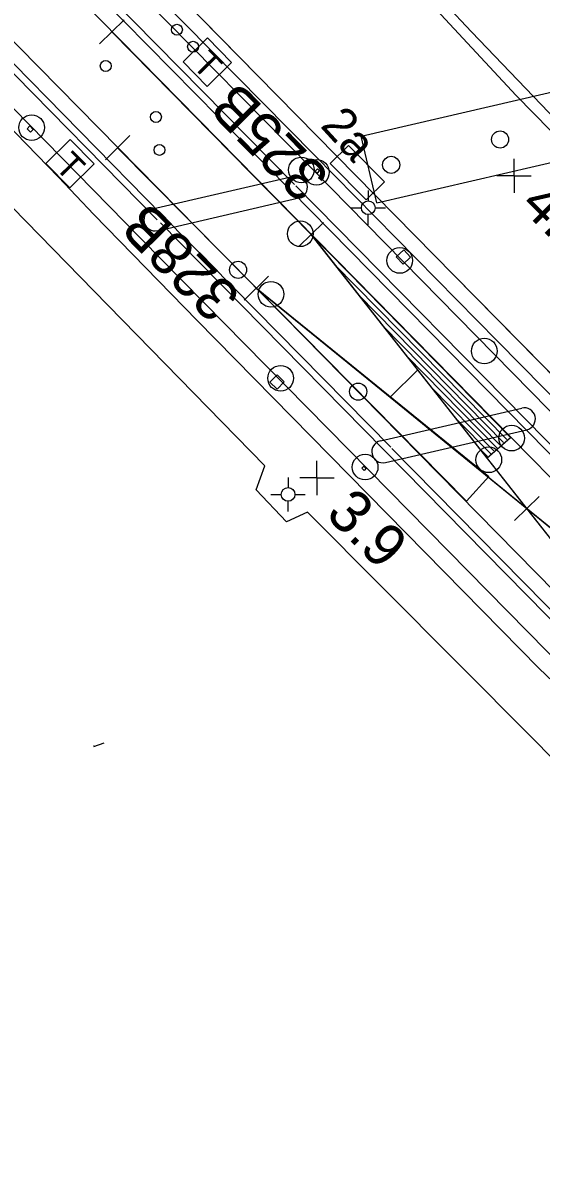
# Model space of a CAD drawing. Extents: x 1596643 to 1597288, y 13057194 to 13057957.
# Drawn here: x 1596964.2 to 1596994.5, y 13057338.6 to 13057405.5 of the extents above; entities that cross this region are included whole.
import ezdxf

# ---------------------------------------------------------------- set-up
doc = ezdxf.new("R2010")
doc.units = 0
for name, color, linetype in [('A Isolerskarv P', 7, 'Continuous'), ('A spårmitt L', 7, 'Continuous'), ('B Vxl-symbol P', 7, 'Continuous'), ('B växel linjevikt 0 L', 7, 'Continuous'), ('B Växel nr T', 7, 'Continuous'), ('BAS belysningsstolpe P', 7, 'Continuous'), ('BAS bro kantbalk ej def L', 7, 'Continuous'), ('BAS bropelare stöd ej def L', 7, 'Continuous'), ('BAS dagvatten brunn P', 7, 'Continuous'), ('BAS jvg-bro kantbalk L', 7, 'Continuous'), ('BAS Level 15', 7, 'Continuous'), ('BAS Level 16', 7, 'Continuous'), ('BAS Level 19', 7, 'Continuous'), ('BAS Level 29', 7, 'Continuous'), ('BAS markytetext T', 7, 'Continuous'), ('BAS registerområdesgräns L', 7, 'Continuous'), ('BAS väg-bro kantbalk L', 7, 'Continuous'), ('BAS väg-bro pelare stöd L', 7, 'Continuous'), ('BAS vägbanekant L', 7, 'Continuous'), ('E ktl sträva stag fundament L', 7, 'Continuous'), ('E ktlstolpe normal centrum P', 7, 'Continuous'), ('E ktlstolpe T', 7, 'Continuous'), ('G telefon fristående P', 7, 'Continuous')]:
    doc.layers.add(name, color=color, linetype=linetype)

msp = doc.modelspace()

# ---------------------------------------------------------------- linework, layer by layer
at = {"layer": 'A Isolerskarv P'}
for centre in [(1596980.436, 13057393.226), (1596980.436, 13057393.226), (1596978.723, 13057389.694), (1596978.723, 13057389.694), (1596992.779, 13057381.288), (1596992.779, 13057381.288), (1596991.445, 13057380.023), (1596991.445, 13057380.023)]:
    msp.add_circle(centre, 0.75, dxfattribs=at)
at = {"layer": 'A spårmitt L'}
for p, q in [((1596970.138, 13057405.733), (1596968.711, 13057404.331)), ((1596970.138, 13057405.733), (1596968.711, 13057404.331)), ((1596969.424, 13057405.032), (1596981.072, 13057393.183)), ((1596969.424, 13057405.032), (1596981.072, 13057393.183)), ((1596980.359, 13057392.482), (1596981.785, 13057393.884)), ((1596980.359, 13057392.482), (1596981.785, 13057393.884)), ((1597006.272, 13057361.158), (1596981.072, 13057393.183)), ((1596981.072, 13057393.183), (1596992.72, 13057381.334)), ((1596981.072, 13057393.183), (1596991.339, 13057380.121)), ((1596981.072, 13057393.183), (1596992.72, 13057381.334)), ((1596981.072, 13057393.183), (1596991.339, 13057380.121)), ((1596982.432, 13057391.435), (1596992.493, 13057381.201)), ((1596982.432, 13057391.435), (1596992.493, 13057381.201)), ((1597009.479, 13057364.305), (1596977.865, 13057390.027)), ((1596983.831, 13057389.656), (1596992.305, 13057381.035)), ((1596983.831, 13057389.656), (1596992.305, 13057381.035)), ((1596985.23, 13057387.876), (1596992.117, 13057380.87)), ((1596985.23, 13057387.876), (1596992.117, 13057380.87)), ((1596986.63, 13057386.096), (1596991.929, 13057380.705)), ((1596986.63, 13057386.096), (1596991.929, 13057380.705)), ((1596988.029, 13057384.316), (1596991.741, 13057380.539)), ((1596988.029, 13057384.316), (1596991.741, 13057380.539)), ((1596989.574, 13057382.387), (1596991.563, 13057380.364)), ((1596989.574, 13057382.387), (1596991.563, 13057380.364)), ((1596991.339, 13057380.121), (1596992.72, 13057381.334)), ((1596991.339, 13057380.121), (1596992.72, 13057381.334)), ((1596990.827, 13057380.757), (1596991.365, 13057380.209)), ((1596990.827, 13057380.757), (1596991.365, 13057380.209))]:
    msp.add_line(p, q, dxfattribs=at)
for points in [[(1596887.988, 13057492.75), (1596889.66, 13057490.516), (1596900.094, 13057476.776), (1596906.53, 13057469.464), (1596928.328, 13057446.663), (1596936.899, 13057437.942), (1596957.336, 13057417.351), (1597001.928, 13057371.989), (1597034.879, 13057338.506), (1597063.764, 13057309.15)], [(1596933.802, 13057434.837), (1596974.458, 13057393.515), (1596978.362, 13057389.553), (1596998.703, 13057368.849), (1597057.437, 13057309.15)]]:
    msp.add_lwpolyline(points, dxfattribs=at)
at = {"layer": 'B Vxl-symbol P'}
for p, q in [((1596987.305, 13057385.289), (1596985.677, 13057383.692)), ((1596993.672, 13057377.17), (1596987.305, 13057385.289)), ((1596985.677, 13057383.692), (1596993.672, 13057377.17)), ((1596985.736, 13057383.643), (1596985.689, 13057383.704)), ((1596992.958, 13057376.47), (1596994.386, 13057377.871)), ((1596993.672, 13057377.17), (1597001.667, 13057370.649)), ((1597000.039, 13057369.052), (1596993.672, 13057377.17))]:
    msp.add_line(p, q, dxfattribs=at)
at = {"layer": 'B växel linjevikt 0 L'}
for p, q in [((1596970.476, 13057398.962), (1596969.052, 13057397.556)), ((1596970.476, 13057398.962), (1596969.052, 13057397.556)), ((1596969.764, 13057398.259), (1596977.873, 13057390.048)), ((1596969.764, 13057398.259), (1596977.873, 13057390.048)), ((1596978.584, 13057390.751), (1596977.161, 13057389.346)), ((1596978.584, 13057390.751), (1596977.161, 13057389.346)), ((1596977.873, 13057390.048), (1596990.152, 13057377.615)), ((1596977.873, 13057390.048), (1596990.152, 13057377.615)), ((1596977.873, 13057390.048), (1596991.45, 13057379.047)), ((1596977.873, 13057390.048), (1596990.152, 13057377.615)), ((1596977.873, 13057390.048), (1596991.45, 13057379.047)), ((1596990.152, 13057377.615), (1596991.45, 13057379.047)), ((1596990.152, 13057377.615), (1596991.45, 13057379.047)), ((1596991.45, 13057379.047), (1596990.152, 13057377.615)), ((1596990.152, 13057377.615), (1596991.45, 13057379.047))]:
    msp.add_line(p, q, dxfattribs=at)
at = {"layer": 'BAS belysningsstolpe P'}
for p, q in [((1596984.403, 13057395.75), (1596984.403, 13057395.15)), ((1596984.403, 13057395.75), (1596984.403, 13057395.15)), ((1596983.403, 13057394.75), (1596984.003, 13057394.75)), ((1596983.403, 13057394.75), (1596984.003, 13057394.75)), ((1596984.403, 13057393.75), (1596984.403, 13057394.352)), ((1596984.403, 13057393.75), (1596984.403, 13057394.352)), ((1596984.802, 13057394.75), (1596985.403, 13057394.75)), ((1596984.802, 13057394.75), (1596985.403, 13057394.75)), ((1596979.72, 13057378.998), (1596979.72, 13057378.398)), ((1596979.72, 13057378.998), (1596979.72, 13057378.398)), ((1596978.72, 13057377.998), (1596979.32, 13057377.998)), ((1596978.72, 13057377.998), (1596979.32, 13057377.998)), ((1596980.119, 13057377.998), (1596980.72, 13057377.998)), ((1596980.119, 13057377.998), (1596980.72, 13057377.998)), ((1596979.72, 13057376.998), (1596979.72, 13057377.6)), ((1596979.72, 13057376.998), (1596979.72, 13057377.6))]:
    msp.add_line(p, q, dxfattribs=at)
for centre in [(1596984.403, 13057394.75), (1596984.403, 13057394.75), (1596979.72, 13057377.998), (1596979.72, 13057377.998)]:
    msp.add_circle(centre, 0.4, dxfattribs=at)
at = {"layer": 'BAS bro kantbalk ej def L'}
for p, q in [((1596969.424, 13057408.898), (1596981.122, 13057397.026)), ((1596979.817, 13057395.82), (1596967.801, 13057408.027)), ((1596968.086, 13057408.307), (1596980.102, 13057396.1)), ((1596960.381, 13057406.522), (1596972.364, 13057394.325)), ((1596972.078, 13057394.045), (1596960.095, 13057406.241)), ((1596971.144, 13057392.936), (1596958.939, 13057405.365)), ((1596981.122, 13057397.026), (1596993.879, 13057384.028)), ((1597006.479, 13057368.704), (1596979.888, 13057395.753)), ((1596980.172, 13057396.033), (1597006.764, 13057368.984)), ((1596998.725, 13057366.965), (1596972.262, 13057393.865)), ((1596985.715, 13057380.76), (1596972.548, 13057394.146)), ((1596984.462, 13057379.392), (1596971.144, 13057392.936)), ((1596993.879, 13057384.028), (1597007.761, 13057369.925)), ((1596999.011, 13057367.246), (1596985.788, 13057380.683)), ((1596997.782, 13057365.837), (1596984.462, 13057379.392))]:
    msp.add_line(p, q, dxfattribs=at)
msp.add_lwpolyline([(1597031.744, 13057325.449), (1597019.684, 13057337.598), (1597007.4, 13057349.92), (1597006.374, 13057349.4), (1597004.663, 13057351.16), (1597005.204, 13057352.357), (1596994.028, 13057363.747)], dxfattribs=at)
at = {"layer": 'BAS bropelare stöd ej def L'}
for p, q in [((1596971.801, 13057394.677), (1596980.06, 13057396.588)), ((1596972.09, 13057393.41), (1596980.351, 13057395.321)), ((1596985.115, 13057381.134), (1596993.373, 13057383.044)), ((1596985.404, 13057379.866), (1596993.665, 13057381.777))]:
    msp.add_line(p, q, dxfattribs=at)
for centre, start, end in [((1596980.204, 13057395.954), 283.02596, 103.02572), ((1596971.948, 13057394.044), 103.02596, 283.02572), ((1596993.518, 13057382.411), 283.02596, 103.02572), ((1596985.261, 13057380.5), 103.02596, 283.02572)]:
    msp.add_arc(centre, 0.65, start, end, dxfattribs=at)
at = {"layer": 'BAS dagvatten brunn P'}
msp.add_line((1596983.762, 13057396.8), (1596983.762, 13057396.8), dxfattribs=at)
msp.add_line((1596983.762, 13057396.8), (1596983.762, 13057396.8), dxfattribs=at)
msp.add_lwpolyline([(1596982.175, 13057397.343), (1596984.28, 13057395.205), (1596985.349, 13057396.257), (1596983.244, 13057398.395)], close=True, dxfattribs=at)
msp.add_lwpolyline([(1596982.175, 13057397.343), (1596984.28, 13057395.205), (1596985.349, 13057396.257), (1596983.244, 13057398.395)], close=True, dxfattribs=at)
at = {"layer": 'BAS jvg-bro kantbalk L'}
for p, q in [((1596970.562, 13057408.681), (1596981.271, 13057397.819)), ((1596981.271, 13057397.819), (1596991.946, 13057386.955)), ((1596991.946, 13057386.955), (1597003.562, 13057375.151))]:
    msp.add_line(p, q, dxfattribs=at)
at = {"layer": 'BAS Level 15'}
for centre in [(1596976.801, 13057391.125), (1596976.801, 13057391.125), (1596983.814, 13057384.004), (1596983.814, 13057384.004)]:
    msp.add_circle(centre, 0.5, dxfattribs=at)
at = {"layer": 'BAS Level 16'}
for p, q in [((1596992.924, 13057396.615), (1596992.924, 13057397.615)), ((1596992.924, 13057396.615), (1596992.924, 13057397.615)), ((1596992.924, 13057396.615), (1596991.924, 13057396.615)), ((1596992.924, 13057396.615), (1596991.924, 13057396.615)), ((1596992.924, 13057396.615), (1596993.924, 13057396.615)), ((1596992.924, 13057396.615), (1596992.924, 13057395.615)), ((1596992.924, 13057396.615), (1596993.924, 13057396.615)), ((1596992.924, 13057396.615), (1596992.924, 13057395.615)), ((1596981.408, 13057378.966), (1596981.408, 13057379.966)), ((1596981.408, 13057378.966), (1596981.408, 13057379.966)), ((1596981.408, 13057378.966), (1596980.408, 13057378.966)), ((1596981.408, 13057378.966), (1596980.408, 13057378.966)), ((1596981.408, 13057378.966), (1596982.408, 13057378.966)), ((1596981.408, 13057378.966), (1596981.408, 13057377.966)), ((1596981.408, 13057378.966), (1596982.408, 13057378.966)), ((1596981.408, 13057378.966), (1596981.408, 13057377.966))]:
    msp.add_line(p, q, dxfattribs=at)
at = {"layer": 'BAS Level 19'}
for points in [[(1596968.373, 13057394.355), (1596966.305, 13057396.53), (1596963.82, 13057399.106), (1596961.488, 13057401.488), (1596960.235, 13057402.746)], [(1596996.958, 13057365.38), (1596994.369, 13057367.841), (1596974.42, 13057388.153), (1596968.373, 13057394.355)]]:
    msp.add_lwpolyline(points, dxfattribs=at)
at = {"layer": 'BAS Level 29'}
for centre in [(1596973.23, 13057405.151), (1596973.23, 13057405.151), (1596974.171, 13057404.159), (1596974.171, 13057404.159), (1596969.068, 13057403.032), (1596969.068, 13057403.032), (1596972.001, 13057400.052), (1596972.001, 13057400.052), (1596972.209, 13057398.13), (1596972.209, 13057398.13)]:
    msp.add_circle(centre, 0.318, dxfattribs=at)
at = {"layer": 'BAS registerområdesgräns L'}
for points in [[(1596968.373, 13057363.272), (1596968.974, 13057363.476)], [(1596968.398, 13057363.323), (1596968.373, 13057363.315)]]:
    msp.add_lwpolyline(points, dxfattribs=at)
at = {"layer": 'BAS väg-bro kantbalk L'}
for points in [[(1596968.373, 13057389.891), (1596958.042, 13057400.461)], [(1596994.028, 13057363.747), (1596980.859, 13057376.954), (1596979.62, 13057376.393), (1596977.859, 13057378.26), (1596978.355, 13057379.663), (1596968.373, 13057389.891)]]:
    msp.add_lwpolyline(points, dxfattribs=at)
at = {"layer": 'BAS väg-bro pelare stöd L'}
for p, q in [((1596984, 13057398.936), (1597005.371, 13057403.887)), ((1596984.906, 13057395.04), (1597006.278, 13057399.991)), ((1596984.906, 13057395.04), (1596984, 13057398.936))]:
    msp.add_line(p, q, dxfattribs=at)
for centre in [(1596992.106, 13057398.735), (1596985.742, 13057397.258)]:
    msp.add_circle(centre, 0.5, dxfattribs=at)
at = {"layer": 'BAS vägbanekant L'}
for p, q in [((1596977.952, 13057402.455), (1596970.491, 13057410.065)), ((1596989.414, 13057390.809), (1596977.952, 13057402.455)), ((1597002.777, 13057377.214), (1596989.414, 13057390.809))]:
    msp.add_line(p, q, dxfattribs=at)
for points in [[(1597133.452, 13057259.15), (1597054.729, 13057339.299), (1596995.848, 13057399.372), (1596990.433, 13057405.034), (1596987.369, 13057408.321), (1596983.644, 13057412.319), (1596981.852, 13057414.308), (1596980.193, 13057416.206), (1596978.635, 13057418.012), (1596978.187, 13057418.58), (1596977.383, 13057419.585), (1596976.059, 13057421.351), (1596974.481, 13057423.493), (1596972.433, 13057426.487), (1596969.826, 13057430.508), (1596968.373, 13057432.851)], [(1596968.373, 13057431.554), (1596968.412, 13057431.491), (1596970.968, 13057427.583), (1596973.443, 13057423.938), (1596974.798, 13057422.081), (1596976.844, 13057419.442), (1596978.382, 13057417.442), (1596980.143, 13057415.392), (1596981.65, 13057413.616), (1596983.899, 13057411.12), (1596986.841, 13057408.015), (1596993.05, 13057401.308), (1597001.071, 13057393.121), (1597017.407, 13057376.512), (1597028.562, 13057365.159), (1597039.891, 13057353.552), (1597050.384, 13057342.909), (1597065.285, 13057327.589), (1597082.629, 13057309.925), (1597099.189, 13057293.124), (1597132.621, 13057259.15)], [(1596977.952, 13057402.455), (1596970.491, 13057410.065)], [(1596989.414, 13057390.809), (1596977.952, 13057402.455)], [(1597002.777, 13057377.214), (1596989.414, 13057390.809)]]:
    msp.add_lwpolyline(points, dxfattribs=at)
at = {"layer": 'E ktl sträva stag fundament L'}
for points in [[(1596964.477, 13057399.367), (1596964.669, 13057399.171), (1596964.834, 13057399.331), (1596964.642, 13057399.528), (1596964.477, 13057399.367)], [(1596980.433, 13057397.016), (1596980.557, 13057396.9), (1596980.679, 13057397.031), (1596980.555, 13057397.147), (1596980.433, 13057397.016)], [(1596981.311, 13057396.884), (1596981.435, 13057396.769), (1596981.557, 13057396.9), (1596981.433, 13057397.016), (1596981.311, 13057396.884)], [(1596986.043, 13057391.88), (1596986.446, 13057391.455), (1596986.882, 13057391.867), (1596986.479, 13057392.293), (1596986.043, 13057391.88)], [(1596979.075, 13057384.995), (1596978.654, 13057384.567), (1596979.078, 13057384.151), (1596979.499, 13057384.578), (1596979.075, 13057384.995)], [(1596984.156, 13057379.657), (1596984.288, 13057379.537), (1596984.166, 13057379.404), (1596984.035, 13057379.525), (1596984.156, 13057379.657)]]:
    msp.add_lwpolyline(points, dxfattribs=at)
at = {"layer": 'E ktlstolpe normal centrum P'}
for centre in [(1596964.738, 13057399.43), (1596964.738, 13057399.43), (1596980.495, 13057396.958), (1596980.495, 13057396.958), (1596981.377, 13057396.822), (1596981.377, 13057396.822), (1596986.245, 13057391.668), (1596986.245, 13057391.668), (1596991.183, 13057386.377), (1596991.183, 13057386.377), (1596979.287, 13057384.786), (1596979.287, 13057384.786), (1596984.222, 13057379.597), (1596984.222, 13057379.597)]:
    msp.add_circle(centre, 0.75, dxfattribs=at)
at = {"layer": 'G telefon fristående P'}
for p, q in [((1596973.594, 13057403.266), (1596975.019, 13057404.669)), ((1596975.019, 13057404.669), (1596976.422, 13057403.244)), ((1596974.997, 13057401.841), (1596973.594, 13057403.266)), ((1596976.422, 13057403.244), (1596974.997, 13057401.841)), ((1596975.008, 13057403.255), (1596975.008, 13057403.255)), ((1596965.568, 13057397.335), (1596966.993, 13057398.738)), ((1596966.993, 13057398.738), (1596968.396, 13057397.313)), ((1596966.971, 13057395.91), (1596965.568, 13057397.335)), ((1596968.396, 13057397.313), (1596966.971, 13057395.91)), ((1596966.982, 13057397.324), (1596966.982, 13057397.324))]:
    msp.add_line(p, q, dxfattribs=at)

# ---------------------------------------------------------------- texts
at = {"layer": 'B Växel nr T'}
for s, rotation, p in [('325B', 134.514, (1596982.241, 13057396.651)), ('328B', 134.532, (1596977.05, 13057389.637))]:
    msp.add_text(s, height=2.499, rotation=rotation, dxfattribs=at).set_placement(p)
at = {"layer": 'BAS markytetext T'}
for s, p in [('4.3', (1596993.182, 13057394.808)), ('3.9', (1596981.844, 13057376.781))]:
    msp.add_text(s, height=2.5, rotation=315, dxfattribs=at).set_placement(p)
at = {"layer": 'E ktlstolpe T'}
msp.add_text('2a', height=1.999, rotation=312.38461, dxfattribs=at).set_placement((1596981.554, 13057399.512))
at = {"layer": 'G telefon fristående P'}
for rotation, p in [(314.53449, (1596974.064, 13057403.031)), (314.53449, (1596974.064, 13057403.031)), (314.53445, (1596966.038, 13057397.1)), (314.53445, (1596966.038, 13057397.1))]:
    msp.add_text('T', height=1.5, rotation=rotation, dxfattribs=at).set_placement(p)

doc.saveas('drawing.dxf')
